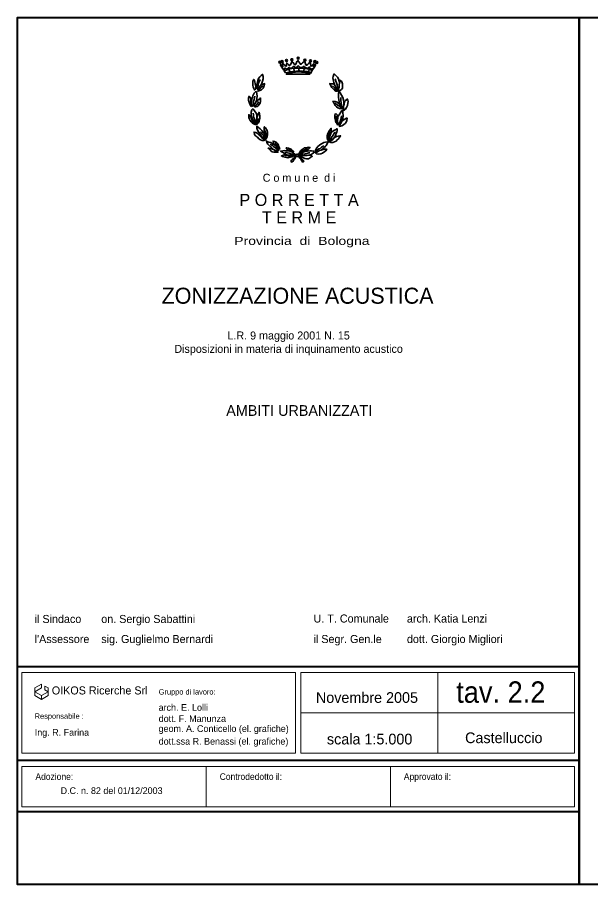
# Model space of a CAD drawing. Extents: x 650468 to 655025, y 889970 to 891591.
# Drawn here: x 650468 to 651540, y 889970 to 891591 of the extents above; entities that cross this region are included whole.
import ezdxf
from ezdxf.enums import TextEntityAlignment as Align

# ---------------------------------------------------------------- set-up
doc = ezdxf.new("R2010")
doc.units = 0
doc.header["$LTSCALE"] = 5.6
doc.layers.add('37', color=7, linetype='Continuous', lineweight=25)
doc.layers.add('61', color=7, linetype='Continuous', lineweight=35)

msp = doc.modelspace()

# ---------------------------------------------------------------- hatches: boundary and pattern name
at = {"layer": '61'}
for points in [[(650971.36, 891512.52, 1), (650971.36, 891508.67, 1)], [(650981.33, 891513.78, 1), (650981.33, 891509.94, 1)], [(650992.99, 891516.63, 1), (650992.99, 891512.78, 1)], [(651005.73, 891512.99, 1), (651005.73, 891509.15, 1)], [(651016.01, 891511.88, 1), (651016.01, 891508.04, 1)], [(650958.78, 891509.04, 1), (650958.78, 891505.19, 1)], [(650962.92, 891510.14, 1), (650962.92, 891506.3, 1)], [(651024.14, 891510.14, 1), (651024.14, 891506.3, 1)], [(651028.13, 891508.72, 1), (651028.13, 891504.87, 1)]]:
    msp.add_hatch(color=256, dxfattribs=at).paths.add_polyline_path(points)

# ---------------------------------------------------------------- linework, layer by layer
at = {"layer": '37', "lineweight": 40}
msp.add_line((650468.28, 890106.08), (651518.28, 890106.08), dxfattribs=at)
at = {"layer": '61'}
for p, q in [((650982.69, 891496.82), (650982.69, 891496.69)), ((650985.31, 891490.22), (650984.69, 891495.89)), ((650994.34, 891490.84), (650994.34, 891496.22)), ((651003.89, 891490.36), (651004.04, 891496.22)), ((650977.94, 891489.24), (650975.19, 891494.16)), ((651012.17, 891488.76), (651013.54, 891493.84)), ((650905.41, 891427.49), (650905.11, 891424.16)), ((650912.65, 891390.68), (650915.86, 891390.84)), ((650931.36, 891361.77), (650934.27, 891366.21)), ((650934.27, 891366.22), (650931.67, 891368.59)), ((650969.81, 891334.92), (650967.04, 891333.95)), ((650984.69, 891339.04), (650982.39, 891338.56))]:
    msp.add_line(p, q, dxfattribs=at)
at = {"layer": '61', "lineweight": 40}
for p, q in [((650468.28, 890377.62), (651518.28, 890377.62)), ((650468.28, 890202.12), (651518.28, 890202.12))]:
    msp.add_line(p, q, dxfattribs=at)
at = {"layer": '61', "lineweight": 13}
for p, q in [((650476.79, 890366.09), (650476.79, 890215.66)), ((650476.79, 890366.09), (650988.24, 890366.09)), ((650988.24, 890366.09), (650988.24, 890215.66)), ((650998.27, 890366.09), (650998.27, 890215.66)), ((650998.27, 890366.09), (651509.74, 890366.09)), ((651254.01, 890366.09), (651254.01, 890215.66)), ((651509.74, 890366.09), (651509.74, 890215.66)), ((650998.28, 890290.87), (651509.75, 890290.87)), ((650476.79, 890215.66), (650988.24, 890215.66)), ((650998.27, 890215.66), (651509.74, 890215.66)), ((650476.79, 890190.59), (650476.79, 890115.39)), ((650476.8, 890190.59), (651509.75, 890190.59)), ((650821.09, 890190.59), (650821.09, 890115.39)), ((651165.41, 890190.59), (651165.41, 890115.39)), ((651509.74, 890190.59), (651509.74, 890115.39)), ((650476.79, 890115.39), (651509.74, 890115.39))]:
    msp.add_line(p, q, dxfattribs=at)
at = {"layer": '61', "lineweight": 40}
msp.add_lwpolyline([(651518.28, 891591.08), (651518.28, 889969.62), (650468.28, 889969.62), (650468.28, 891591.08)], close=True, dxfattribs=at)
for points in [[(652568.28, 889969.62), (651518.28, 889969.62), (651518.28, 891591.08)], [(651518.28, 891591.08), (652568.28, 891591.08), (652568.28, 889969.62)]]:
    msp.add_lwpolyline(points, dxfattribs=at)
at = {"layer": '61'}
for points in [[(650982.07, 891508.54), (650980.87, 891506.49), (650978.54, 891502.06), (650977.61, 891501.12), (650976.41, 891501.12), (650975.79, 891501.89), (650974.87, 891502.84), (650973.97, 891504.26), (650971.81, 891505.84), (650971.49, 891503.16), (650971.34, 891501.12), (650971.19, 891499.84), (650969.67, 891499.52), (650968.29, 891501.44), (650966.27, 891503.32), (650964.14, 891505.24), (650964.31, 891502.69), (650964.59, 891500.16), (650964.44, 891498.74), (650961.99, 891502.36), (650960.59, 891503.32), (650959.37, 891503.16)], [(650959.37, 891503.16), (650964.44, 891495.09), (650966.14, 891492.42), (650967.07, 891493.06), (650967.21, 891493.54), (650966.89, 891494.62), (650967.21, 891495.42), (650967.81, 891496.06), (650969.67, 891495.89), (650970.59, 891495.09), (650970.89, 891493.96), (650974.27, 891495.26), (650974.27, 891495.74), (650974.27, 891496.22), (650974.57, 891496.52), (650975.19, 891496.99), (650975.49, 891497.16), (650976.41, 891497.16), (650977.01, 891496.82), (650977.61, 891496.22), (650982.69, 891496.69)], [(651026.29, 891502.69), (651025.37, 891502.69), (651024.29, 891502.06), (651023.97, 891500.46), (651023.67, 891498.59), (651022.77, 891497.16), (651021.97, 891497.94), (651021.84, 891499.69), (651022.14, 891502.36), (651021.84, 891504.26), (651019.21, 891501.44), (651017.84, 891499.84), (651017.21, 891499.69), (651016.77, 891499.69), (651016.47, 891500.64), (651015.99, 891503.32), (651015.99, 891505.84), (651014.77, 891506.66), (651012.47, 891504.74), (651010.49, 891503.02), (651009.69, 891501.89), (651008.47, 891501.44), (651007.41, 891502.22), (651006.61, 891504.12), (651005.41, 891507.76), (651004.19, 891508.39), (651001.41, 891505.84), (650999.11, 891503.96), (650997.89, 891503.32), (650997.11, 891503.32), (650995.89, 891505.24), (650994.34, 891508.06), (650992.67, 891510.44), (650990.81, 891508.24), (650989.29, 891504.62), (650988.37, 891502.69), (650986.99, 891502.36), (650985.77, 891503.49), (650983.77, 891506.49), (650982.07, 891508.54)], [(650982.69, 891496.82), (650982.69, 891497.32), (650982.69, 891497.94), (650982.99, 891498.44), (650983.77, 891498.92), (650984.69, 891499.06), (650985.61, 891498.92), (650986.54, 891498.44), (650986.54, 891497.16), (650991.44, 891497.16), (650991.44, 891497.62), (650991.44, 891499.06), (650991.61, 891499.69), (650992.37, 891499.99), (650993.44, 891500.32), (650994.51, 891499.69), (650995.44, 891498.74), (650995.44, 891497.79), (651001.87, 891497.32), (651001.87, 891497.62), (651001.87, 891498.12), (651002.17, 891498.92), (651002.67, 891499.22), (651003.71, 891499.22), (651004.79, 891498.92), (651005.41, 891497.46), (651011.69, 891496.06), (651011.69, 891496.69), (651012.31, 891497.46), (651013.09, 891498.12), (651014.31, 891498.12), (651014.77, 891496.99), (651014.77, 891495.26), (651018.29, 891494.29), (651018.47, 891494.94), (651019.39, 891495.42), (651020.59, 891493.96), (651020.14, 891492.74), (651023.67, 891497.79), (651026.29, 891502.69)], [(650916.31, 891467.96), (650917.69, 891472.86), (650919.07, 891476.69), (650921.54, 891479.96), (650924.14, 891482.52), (650926.59, 891484.44), (650927.37, 891480.62), (650927.37, 891476.04), (650926.44, 891471.92), (650925.07, 891467.96), (650923.24, 891464.16), (650925.67, 891465.62), (650930.29, 891467.34), (650930.14, 891465.89), (650928.89, 891461.82), (650927.37, 891458.79), (650924.61, 891455.79), (650921.21, 891454.06), (650918.17, 891452.94), (650917.54, 891457.06)], [(650917.39, 891457.06), (650916.01, 891460.09), (650915.71, 891463.54), (650916.31, 891467.96)], [(650917.39, 891457.06), (650917.39, 891460.69), (650918.01, 891464.49), (650919.07, 891467.82), (650920.17, 891470.82), (650921.99, 891474.76)], [(650923.24, 891464.16), (650920.01, 891460.52), (650917.54, 891457.06)], [(650918.17, 891452.94), (650920.47, 891456.59), (650922.14, 891457.99), (650924.14, 891460.69), (650926.89, 891462.92)], [(651061.11, 891465.29), (651063.11, 891461.19), (651065.27, 891458.04), (651066.31, 891455.64), (651067.39, 891453.59), (651064.34, 891455.16), (651062.51, 891457.06), (651060.67, 891459.12), (651058.49, 891461.49), (651057.29, 891462.94)], [(651068.01, 891455.56), (651066.49, 891459.76), (651065.87, 891464.66), (651064.97, 891468.46), (651063.74, 891471.46), (651062.34, 891476.04)], [(651070.17, 891468.62), (651069.87, 891464.04), (651069.41, 891460.39), (651068.64, 891457.56), (651067.39, 891453.59)], [(650905.11, 891424.16), (650908.19, 891427.49), (650909.44, 891430.16), (650909.71, 891434.29), (650910.79, 891437.76), (650911.27, 891440.62), (650912.01, 891443.46)], [(650914.01, 891432.24), (650911.87, 891429.06), (650910.19, 891426.06)], [(650912.01, 891423.86), (650914.17, 891426.54), (650915.84, 891428.44), (650918.17, 891430.96), (650919.39, 891432.89)], [(651072.77, 891423.26), (651070.01, 891424.99), (651066.31, 891426.72), (651062.01, 891430.36)], [(651079.04, 891417.06), (651076.14, 891421.82), (651074.29, 891427.02), (651073.54, 891431.49), (651073.07, 891435.74), (651072.47, 891441.42)], [(650915.84, 891390.84), (650918.77, 891394.02), (650919.99, 891397.16), (650921.54, 891402.56), (650921.39, 891406.32), (650920.91, 891411.09), (650919.99, 891413.76), (650917.69, 891408.24), (650916.31, 891405.24), (650915.57, 891401.14), (650915.84, 891407.14), (650914.91, 891411.24), (650912.64, 891414.42), (650910.34, 891418.04), (650908.49, 891420.26), (650906.67, 891418.36), (650905.41, 891413.94), (650905.41, 891411.09), (650905.41, 891406.96), (650906.34, 891403.49), (650908.79, 891398.74), (650911.39, 891394.64), (650912.64, 891390.69), (650911.87, 891392.26), (650910.17, 891394.16), (650908.01, 891397.16), (650906.19, 891400.64), (650904.67, 891404.44), (650900.67, 891409.19), (650901.11, 891403.96), (650902.21, 891400.94), (650903.14, 891398.42), (650905.27, 891395.74), (650906.94, 891393.69), (650909.71, 891392.12), (650912.64, 891390.69)], [(651075.21, 891420.54), (651072.77, 891423.26), (651071.99, 891425.62), (651070.31, 891428.79)], [(651078.29, 891426.72), (651077.99, 891424.02), (651077.67, 891422.62), (651079.04, 891417.06)], [(650912.94, 891393.14), (650912.49, 891396.22), (650911.57, 891401.26), (650909.87, 891405.39), (650909.44, 891408.72), (650908.79, 891412.22)], [(650915.57, 891401.14), (650914.61, 891396.86), (650914.01, 891394.02), (650911.87, 891392.26)], [(650914.01, 891394.02), (650915.84, 891390.84), (650916.94, 891394.16), (650918.29, 891398.26), (650918.47, 891402.06)], [(651066.27, 891391.16), (651065.71, 891394.96), (651064.97, 891400.49), (651064.34, 891404.12), (651064.34, 891406.82)], [(651067.39, 891405.42), (651067.09, 891402.24), (651066.79, 891399.39), (651066.79, 891397.16), (651067.39, 891394.02)], [(651075.39, 891397.64), (651073.69, 891393.84), (651070.34, 891389.09), (651070.47, 891392.89), (651071.39, 891396.22), (651072.47, 891400.16), (651073.24, 891403.34), (651074.14, 891407.14)], [(650934.27, 891366.22), (650935.31, 891368.42), (650935.61, 891370.62), (650935.61, 891373.14), (650935.49, 891376.32), (650935.01, 891379.49), (650933.94, 891381.69), (650932.09, 891384.22), (650930.41, 891386.59), (650929.64, 891384.22), (650929.34, 891379.96), (650929.21, 891377.29), (650929.64, 891373.46), (650927.04, 891375.86), (650924.89, 891379.64), (650921.99, 891382.49), (650918.61, 891385.34), (650915.84, 891387.56), (650915.84, 891385.96), (650916.01, 891383.59), (650917.21, 891380.44), (650918.91, 891377.12), (650920.77, 891373.79), (650923.04, 891370.46), (650925.21, 891367.76), (650928.71, 891365.09), (650931.34, 891361.79), (650930.41, 891362.89), (650927.19, 891364.44), (650924.27, 891366.69), (650921.99, 891369.22), (650919.69, 891371.42), (650917.54, 891373.79), (650913.84, 891375.52), (650910.64, 891376.49), (650911.71, 891372.36), (650913.54, 891369.84), (650916.94, 891366.84), (650919.69, 891363.99), (650922.59, 891362.09)], [(650929.64, 891373.46), (650931.67, 891368.59), (650931.67, 891364.44), (650930.41, 891362.89), (650929.81, 891367.76), (650927.79, 891370.62), (650925.81, 891372.99), (650923.67, 891375.22), (650922.31, 891377.12)], [(650934.27, 891366.22), (650932.71, 891370.14), (650932.41, 891374.44), (650931.67, 891379.34)], [(651050.39, 891359.86), (651048.54, 891364.62), (651049.64, 891368.09), (651050.71, 891373.96), (651052.07, 891376.16), (651052.84, 891377.44)], [(651054.99, 891375.86), (651053.91, 891373.96), (651052.99, 891370.62), (651052.39, 891369.22), (651051.31, 891365.56), (651050.39, 891362.72), (651050.39, 891359.86)], [(651051.17, 891358.32), (651053.29, 891361.94), (651055.44, 891366.22), (651058.21, 891371.12), (651060.67, 891375.06), (651062.99, 891376.16)], [(650922.59, 891362.09), (650925.67, 891360.96), (650928.89, 891360.82), (650931.34, 891361.79)], [(650956.81, 891341.86), (650954.04, 891344.39), (650951.59, 891346.26), (650949.29, 891347.89), (650947.14, 891349.62), (650944.84, 891351.34), (650942.84, 891352.44), (650940.99, 891353.86)], [(650958.64, 891344.72), (650958.04, 891347.06), (650957.11, 891349.29), (650956.19, 891351.82), (650955.11, 891354.06), (650953.87, 891355.94), (650952.04, 891357.52), (650948.81, 891358.79), (650945.91, 891359.89), (650946.07, 891358.94), (650946.67, 891356.42), (650947.29, 891353.74)], [(650947.31, 891353.73), (650953.45, 891348.33), (650954.29, 891347.15), (650956.82, 891346.13), (650958.66, 891344.7)], [(650958.64, 891344.72), (650955.71, 891348.52), (650953.74, 891351.04), (650952.04, 891353.86), (650950.51, 891355.46), (650949.41, 891355.94)], [(651025.11, 891340.59), (651028.81, 891342.64), (651031.39, 891345.16), (651034.31, 891346.14), (651036.77, 891348.66), (651041.09, 891350.56)], [(651051.17, 891358.32), (651054.37, 891360.19), (651056.84, 891361.79)], [(650958.64, 891344.72), (650956.81, 891346.14), (650954.29, 891347.16)], [(650986.54, 891335.54), (650983.61, 891337.62), (650981.17, 891339.49), (650977.61, 891340.76), (650974.41, 891341.24), (650971.04, 891341.56), (650967.67, 891341.86), (650964.44, 891341.69), (650961.54, 891341.09), (650960.29, 891340.94), (650961.69, 891339.66), (650963.81, 891338.86), (650965.51, 891338.06), (650967.81, 891336.32), (650969.79, 891334.92)], [(650967.04, 891333.96), (650965.04, 891333.49), (650962.91, 891332.39), (650961.69, 891332.06), (650963.81, 891331.12), (650966.27, 891330.16), (650968.59, 891329.39), (650971.34, 891328.92), (650973.49, 891328.74), (650975.64, 891328.92), (650978.11, 891329.39), (650981.01, 891330.16), (650983.77, 891331.44), (650979.17, 891333.32), (650981.31, 891333.49), (650984.84, 891333.79), (650986.54, 891335.54)], [(650967.04, 891333.96), (650969.49, 891333.02), (650971.81, 891332.54), (650974.27, 891331.92), (650977.47, 891331.59), (650980.87, 891331.59), (650983.77, 891331.44)], [(650986.54, 891335.54), (650982.69, 891335.22), (650980.39, 891335.42), (650978.27, 891336.32), (650975.94, 891337.14), (650973.34, 891337.62), (650970.89, 891338.56), (650968.29, 891338.69)], [(650979.17, 891333.32), (650975.34, 891333.32), (650972.27, 891333.79), (650969.79, 891334.92)], [(650984.69, 891339.04), (650982.87, 891341.56), (650980.71, 891344.09), (650978.27, 891345.52), (650974.87, 891346.29), (650971.64, 891347.09), (650970.71, 891347.39), (650971.49, 891345.66), (650973.04, 891343.14), (650974.87, 891342.66), (650976.87, 891342.52), (650979.39, 891340.14)], [(650983.57, 891338.79), (650980.57, 891341.86), (650977.94, 891343.62), (650974.87, 891345.19)], [(650979.4, 891340.13), (650981.18, 891339.49), (650982.41, 891338.55), (650984.69, 891339.03)], [(650990.39, 891335.22), (650989.47, 891333.79), (650988.67, 891332.54), (650988.37, 891330.32)], [(650993.29, 891334.12), (650998.04, 891338.24), (651000.64, 891340.59), (651003.71, 891342.82), (651007.24, 891344.72), (651010.49, 891345.19)], [(650993.59, 891330.94), (650998.21, 891334.29), (651001.57, 891335.22), (651006.01, 891335.84), (651008.97, 891336.64), (651012.77, 891337.62), (651014.61, 891337.94)], [(650993.59, 891330.94), (650998.81, 891332.22), (651004.19, 891332.86), (651009.57, 891332.54), (651012.31, 891333.16)], [(651004.19, 891339.49), (651001.41, 891338.56), (650999.27, 891336.96), (650996.97, 891335.42), (650995.89, 891333.79), (650993.74, 891332.22)], [(651035.94, 891343.02), (651033.09, 891341.86), (651031.27, 891340.74), (651029.24, 891339.79), (651028.01, 891339.02), (651027.11, 891338.36), (651026.04, 891337.44)]]:
    msp.add_lwpolyline(points, dxfattribs=at)
for points in [[(650969.67, 891487.04), (650967.07, 891491.29), (650970.59, 891492.56), (650975.19, 891494.16), (650981.01, 891495.26), (650987.91, 891496.06), (650995.14, 891496.22), (651001.27, 891496.06), (651006.19, 891495.74), (651010.79, 891494.79), (651015.09, 891493.36), (651019.39, 891491.76), (651015.99, 891486.39), (651014.14, 891488.29), (651009.57, 891489.56), (651001.14, 891490.36), (650996.04, 891490.84), (650989.89, 891490.36), (650982.99, 891489.72), (650977.94, 891489.24), (650973.34, 891488.14)], [(650974.71, 891486.39), (650981.64, 891487.84), (650987.91, 891488.44), (650994.34, 891488.92), (650999.41, 891488.76), (651006.79, 891487.99), (651012.17, 891487.19), (651014.99, 891485.04), (650971.11, 891484.74)], [(651066.19, 891452.16), (651067.39, 891453.59), (651072.01, 891455.02), (651073.99, 891455.94), (651075.87, 891458.96), (651076.01, 891462.12), (651076.01, 891466.86), (651075.21, 891468.79), (651074.17, 891471.76), (651072.01, 891473.52), (651071.57, 891471.64), (651070.17, 891468.62), (651069.87, 891471.76), (651068.64, 891476.04), (651066.49, 891479.54), (651064.34, 891481.89), (651060.19, 891485.39), (651059.41, 891484.26), (651058.19, 891480.64), (651058.07, 891478.26), (651058.19, 891474.94), (651058.81, 891471.76), (651059.59, 891469.12), (651061.11, 891465.29), (651057.89, 891466.86), (651054.69, 891467.02), (651052.21, 891467.19), (651054.21, 891463.09), (651056.21, 891459.92), (651058.19, 891457.56), (651060.67, 891455.16), (651063.44, 891452.96)], [(650911.39, 891472.86), (650912.19, 891470.66), (650912.94, 891467.02), (650913.87, 891463.24), (650914.17, 891460.36), (650913.69, 891457.54), (650911.27, 891455.46), (650910.19, 891457.84), (650909.11, 891461.02), (650908.61, 891463.84), (650908.34, 891467.49), (650908.61, 891471.29), (650909.71, 891474.44), (650910.19, 891475.09)], [(650905.11, 891424.16), (650902.51, 891428.59), (650901.41, 891432.39), (650900.51, 891436.04), (650900.51, 891439.82), (650901.41, 891443.46), (650904.34, 891439.34), (650904.67, 891436.82), (650904.81, 891432.39), (650905.41, 891427.49), (650906.04, 891431.92), (650906.04, 891435.09), (650906.79, 891439.82), (650907.59, 891441.72), (650908.49, 891444.26), (650909.71, 891447.12), (650911.11, 891449.02), (650913.39, 891451.54), (650915.09, 891452.32), (650915.84, 891448.36), (650916.47, 891443.62), (650916.01, 891439.49), (650915.24, 891435.42), (650914.01, 891432.24), (650916.17, 891434.44), (650918.47, 891436.96), (650921.39, 891439.04), (650922.47, 891440.32), (650922.47, 891436.66), (650922.47, 891433.19), (650921.84, 891430.64), (650920.29, 891428.44), (650918.31, 891425.89), (650916.31, 891424.34), (650914.01, 891423.86), (650912.01, 891423.86), (650910.19, 891426.06)], [(651075.21, 891420.54), (651070.47, 891420.42), (651066.91, 891421.64), (651064.47, 891424.02), (651062.47, 891426.09), (651060.94, 891428.94), (651058.79, 891432.26), (651057.87, 891434.32), (651062.17, 891433.69), (651065.71, 891432.42), (651070.31, 891428.79), (651069.51, 891433.36), (651068.77, 891437.79), (651068.61, 891440.96), (651068.61, 891448.09), (651069.69, 891453.62), (651071.54, 891449.96), (651073.99, 891445.54), (651076.29, 891441.26), (651078.29, 891434.62), (651078.29, 891426.72), (651078.89, 891428.94), (651079.51, 891432.89), (651081.97, 891435.89), (651083.64, 891437.46), (651084.89, 891438.59), (651085.81, 891436.36), (651086.27, 891433.52), (651086.11, 891430.52), (651085.34, 891426.42), (651083.64, 891422.62), (651081.37, 891419.62), (651079.04, 891417.06)], [(651067.24, 891389.72), (651065.27, 891392.59), (651063.57, 891394.49), (651062.51, 891397.49), (651062.01, 891401.26), (651061.27, 891403.49), (651061.57, 891408.09), (651062.19, 891410.62), (651064.97, 891410.14), (651066.64, 891408.09), (651067.39, 891405.42), (651069.69, 891408.72), (651072.47, 891413.94), (651074.91, 891416.94), (651076.31, 891416.16), (651076.61, 891412.82), (651077.24, 891407.76), (651076.61, 891402.06), (651075.39, 891397.64), (651080.44, 891400.79), (651083.51, 891402.56), (651084.57, 891402.86), (651083.97, 891397.64), (651081.19, 891393.22), (651077.99, 891389.89), (651074.47, 891387.99), (651070.17, 891387.19), (651070.34, 891389.09), (651067.39, 891394.02), (651067.39, 891390.52)], [(651050.39, 891359.86), (651047.61, 891362.56), (651047.01, 891365.26), (651047.01, 891369.69), (651047.94, 891372.54), (651049.64, 891376.34), (651051.61, 891379.49), (651053.61, 891382.02), (651054.84, 891383.79), (651054.99, 891381.24), (651054.99, 891378.39), (651054.99, 891375.86), (651057.77, 891378.06), (651061.11, 891380.14), (651062.84, 891381.06), (651064.81, 891382.82), (651065.89, 891382.66), (651065.74, 891379.82), (651065.44, 891376.64), (651063.74, 891372.84), (651063.59, 891370.94), (651061.29, 891367.46), (651059.29, 891364.79), (651056.81, 891361.76), (651062.19, 891366.99), (651064.51, 891368.09), (651068.19, 891369.06), (651070.64, 891369.52), (651072.49, 891369.52), (651071.71, 891368.09), (651069.57, 891366.04), (651067.89, 891363.52), (651066.04, 891361.79), (651063.89, 891359.39), (651060.81, 891358.14), (651057.59, 891357.34), (651054.37, 891357.19), (651051.17, 891358.32)], [(650956.19, 891343.29), (650955.11, 891345.99), (650953.44, 891348.34), (650951.11, 891350.56), (650948.67, 891352.62), (650945.91, 891354.82), (650942.21, 891357.34), (650937.94, 891357.69), (650935.19, 891358.94), (650933.79, 891359.74), (650934.69, 891356.89), (650936.54, 891354.19), (650938.69, 891351.66), (650940.69, 891349.44), (650943.01, 891347.56), (650946.67, 891343.92), (650941.77, 891345.34), (650937.31, 891346.26), (650936.71, 891346.44), (650939.31, 891343.74), (650942.21, 891341.39), (650944.69, 891339.96), (650947.74, 891339.16), (650952.04, 891338.86), (650955.29, 891339.02), (650949.59, 891341.39), (650946.67, 891343.92), (650950.67, 891342.34), (650953.87, 891342.02), (650956.81, 891341.86)], [(651025.11, 891340.59), (651026.19, 891344.24), (651027.87, 891347.06), (651029.87, 891349.76), (651032.61, 891351.96), (651035.39, 891353.86), (651038.17, 891355.29), (651041.09, 891357.02), (651043.99, 891357.66), (651048.41, 891358.46), (651049.04, 891358.32), (651047.51, 891355.29), (651046.91, 891353.56), (651045.51, 891351.49), (651044.14, 891350.09), (651042.44, 891348.04), (651040.77, 891346.92), (651035.94, 891342.99), (651039.69, 891344.06), (651042.61, 891344.39), (651046.14, 891344.54), (651046.44, 891343.42), (651042.61, 891340.12), (651038.31, 891337.44), (651035.24, 891335.84), (651031.27, 891335.36), (651027.11, 891336.02), (651026.04, 891337.44)], [(650990.39, 891335.22), (650991.74, 891335.54), (650993.29, 891334.12), (650993.74, 891332.22), (650993.59, 891330.94), (650990.54, 891330.64), (650988.37, 891330.32), (650986.69, 891326.54), (650984.69, 891324.64), (650983.31, 891321.79), (650981.77, 891320.36), (650979.47, 891321.32), (650979.94, 891323.36), (650981.77, 891324.76), (650983.31, 891326.86), (650985.94, 891329.22), (650988.37, 891330.32), (650986.37, 891331.12), (650986.24, 891332.69), (650988.07, 891334.92)], [(650993.29, 891334.12), (650995.27, 891337.94), (650997.71, 891341.24), (651000.04, 891343.46), (651002.34, 891345.52), (651004.49, 891346.92), (651007.24, 891347.39), (651010.31, 891348.04), (651013.09, 891348.19), (651015.24, 891348.04), (651014.61, 891347.39), (651013.21, 891345.99), (651011.54, 891344.09), (651008.47, 891342.34), (651004.19, 891339.49), (651006.94, 891340.29), (651010.79, 891340.94), (651014.61, 891341.39), (651018.14, 891341.39), (651021.97, 891341.09), (651022.77, 891339.49), (651021.97, 891337.62), (651019.51, 891336.02), (651017.07, 891334.76), (651012.31, 891333.16), (651017.39, 891332.86), (651019.21, 891331.26), (651016.14, 891329.22), (651012.17, 891326.86), (651008.79, 891326.86), (651005.71, 891327.49), (651002.81, 891328.59), (651000.34, 891329.69), (650998.64, 891330.94), (650993.59, 891330.94), (650993.74, 891332.22)], [(650993.59, 891330.94), (650999.41, 891327.16), (651000.94, 891325.09), (651003.41, 891322.56), (651002.49, 891320.84), (651001.27, 891320.36), (650999.89, 891323.04), (650998.04, 891325.74), (650996.37, 891327.96), (650994.67, 891329.52)]]:
    msp.add_lwpolyline(points, close=True, dxfattribs=at)
at = {"layer": '61', "lineweight": 13}
for points in [[(650513.18, 890344.53), (650500.77, 890337.39), (650500.77, 890330.22), (650513.18, 890337.39)], [(650513.18, 890323.06), (650500.77, 890330.22), (650500.77, 890323.06), (650513.18, 890315.92)], [(650525.59, 890330.22), (650513.18, 890323.06), (650513.18, 890315.92), (650525.59, 890323.06)], [(650525.59, 890337.39), (650519.38, 890340.96), (650519.38, 890333.81), (650525.59, 890330.22)]]:
    msp.add_lwpolyline(points, close=True, dxfattribs=at)
at = {"layer": '61'}
for centre in [(650971.36, 891510.59), (650981.33, 891511.86), (650992.99, 891514.7), (651005.73, 891511.07), (651016.01, 891509.96), (650958.78, 891507.11), (650962.92, 891508.22), (651024.14, 891508.22), (651028.13, 891506.8)]:
    msp.add_circle(centre, 1.92, dxfattribs=at)

# ---------------------------------------------------------------- texts
for s, height, p in [('C o m u n e  d i', 15, (650994.78, 891283.71)), ('P O R R E T T A', 22.56, (650994.79, 891238.51)), ('T E R M E', 22.56, (650994.78, 891205.91)), ('ZONIZZAZIONE ACUSTICA', 30, (650991.93, 891055.65)), ('L.R. 9 maggio 2001 N. 15', 15, (650975.18, 890988.83)), ('Disposizioni in materia di inquinamento acustico', 15, (650975.18, 890963.83)), ('AMBITI URBANIZZATI', 20.06, (650994.98, 890846.01)), ('Novembre 2005', 20.06, (651121.55, 890309.41)), ('Castelluccio', 20.06, (651377.26, 890234.19))]:
    msp.add_text(s, height=height, dxfattribs=at).set_placement(p, align=Align.CENTER)
at = {"layer": '61', "width": 1.3}
msp.add_text('Provincia  di  Bologna', height=15.04, dxfattribs=at).set_placement((651000.02, 891165.61), align=Align.CENTER)
at = {"layer": '61'}
for s, height, p in [('il Sindaco', 15.04, (650500.6, 890458.83)), ('on. Sergio Sabattini', 15.04, (650625.07, 890458.83)), ('U. T. Comunale', 15.04, (651021.78, 890459.63)), ('arch. Katia Lenzi', 15.04, (651196.33, 890459.63)), ("l'Assessore", 15.04, (650500.63, 890421.31)), ('sig. Guglielmo Bernardi', 15.04, (650625.1, 890421.31)), ('il Segr. Gen.le', 15.04, (651021.78, 890421.31)), ('dott. Giorgio Migliori', 15.04, (651196.33, 890421.31)), ('OIKOS Ricerche Srl', 15.04, (650532.66, 890325.21)), ('arch. E. Lolli', 12.54, (650732.23, 890294.61)), ('dott. F. Manunza', 12.54, (650732.4, 890273.73)), ('geom. A. Conticello (el. grafiche)', 12.54, (650732.18, 890255.03)), ('Ing. R. Farina', 12.54, (650500.76, 890247.99)), ('scala 1:5.000     ', 20.06, (651046.83, 890231.76)), ('dott.ssa R. Benassi (el. grafiche)', 12.54, (650732.43, 890231.31)), ('D.C. n. 82 del 01/12/2003', 12.5, (650549.14, 890139.1))]:
    msp.add_text(s, height=height, dxfattribs=at).set_placement(p)
at = {"layer": '61', "width": 0.95}
for s, height, p in [('tav. 2.2', 40, (651288.4, 890309.63)), ('Gruppo di lavoro:', 10.03, (650732.46, 890325.03)), ('Responsabile :', 10.03, (650500.73, 890279.69)), ('Adozione:', 12.5, (650502.06, 890165.39)), ('Controdedotto il:', 12.5, (650846.43, 890165.39)), ('Approvato il:', 12.5, (651190.5, 890165.39))]:
    msp.add_text(s, height=height, dxfattribs=at).set_placement(p)

doc.saveas('drawing.dxf')
